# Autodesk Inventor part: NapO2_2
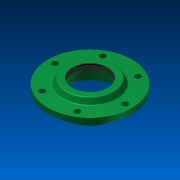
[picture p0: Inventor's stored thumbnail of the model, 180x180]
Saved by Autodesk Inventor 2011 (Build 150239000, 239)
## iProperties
Created: 2011-05
Part Number: NapO2_2
Document SubType Name: Modeling
Designer: 904Chiaki
Density: 1 g/cm^3
Author: 904Chiaki
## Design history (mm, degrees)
sketch "Sketch1"
  geometry: C1 r 79 at (-7.164, 6.167); 1 further point
  constraints: 1 centre point
  dimensions: "d0" = 158 diameter of C1
extrude "Extrusion1" new body sketch "Sketch1" distance "d1" = 10; taper "d2" = 0 deg
sketch "Sketch2"
  geometry: C1 r 50 at (0, 0); 1 further point
  constraints: 1 centre point
  dimensions: "d4" = 100 diameter of C1
extrude "Extrusion2" join sketch "Sketch2" distance "d5" = 10; taper "d6" = 0 deg
sketch "Sketch3"
  geometry: C1 r 79 at (0, 0) reference; C2 r 50 at (0, 0); 1 further point
  constraints: 1 centre point, 1 coincident
  dimensions: "d7" = 100 diameter of C2
extrude "Extrusion3" cut sketch "Sketch3" distance "d8" = 8; taper "d9" = 0 deg
chamfer "Chamfer1" distance "d10" = 10; stored, may be unused: second distance "d11" = 5, angle "d12" = 45 deg
workplane "Work Plane1"
  workaxis "Work Axis1"
fillet "Fillet1" dims "d17" = 2
fillet "Fillet2" dims "d18" = 2
sketch "Sketch5"
  geometry: C1 r 50 at (0, 0) reference; C2 r 79 at (0, 0) reference; C3 r 54 at (0, 0); 1 further point
  constraints: 1 centre point, 1 coincident
  dimensions: "d19" = 108 diameter of C3
extrude "Extrusion5" join sketch "Sketch5" distance "d20" = 2; taper "d21" = 0 deg
sketch "Sketch6"
  geometry: C1 r 50 at (0, 0) reference; C2 r 54 at (0, 0) reference; C3 r 55 at (0, 0); 1 further point
  constraints: 1 centre point, 1 coincident
  dimensions: "d22" = 110 diameter of C3
extrude "Extrusion6" join sketch "Sketch6" distance "d23" = 18.5; taper "d24" = 0 deg
chamfer "Chamfer2" distance "d26" = 1; stored, may be unused: second distance "d27" = 5, angle "d28" = 45 deg
chamfer "Chamfer3" distance "d29" = 1; stored, may be unused: second distance "d30" = 5, angle "d31" = 45 deg
workpoint "Work Point1"
workpoint "Work Point2"
workpoint "Work Point3"
workpoint "Work Point4"
workpoint "Work Point5"
workpoint "Work Point6"
workplane "Work Plane2"
sketch "Sketch10"
  geometry: C1 r 50 at (0, 0) reference; C2 r 33.25 at (0, 0); 1 further point
  constraints: 1 centre point, 1 coincident
  dimensions: "d43" = 66.5 diameter of C2
extrude "Extrusion9" cut sketch "Sketch10" stored distance "d44" = 2; taper "d45" = 0 deg
sketch "Sketch11"
  geometry: L1 (14, 42)-(17.25, 42); L2 (18.5, 33.25)-(17.25, 42); L3 (9.5, 33.25)-(10.75, 42); L4 (14, 42)-(10.75, 42); L5 (18.5, 33.25)-(9.5, 33.25); L6 (-25.6, 0)-(27.6, 0) reference; 1 further point
  constraints: 10 end point
  dimensions: "d47" = 3.25 distance of L1.start L1.end
revolve "Revolution1" sketch "Sketch11" stored, may be unused: angle "d49" = 90 deg
fillet "Fillet4" dims "d50" = 5
node "Hole2"
body "Solid1"
sketch "Sketch12"
  geometry: 6 further points
hole "Hole1" sketch "Sketch12" diameter "d51" = 11; stored, may be unused: countersink angle "d55" = 90 deg, drill point angle "d57" = 0 deg; dims "d52" = 6, "d53" = 4, "d54" = 2, "d56" = 8
other parameters: "d13" = 90 deg
